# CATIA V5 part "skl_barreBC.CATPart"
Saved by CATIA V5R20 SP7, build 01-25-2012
Part number: skl_barreBC
Publications: "Axe pivot BC/DC", "Axe pivot BC/AB", "Plan BC"
Bounding box of the stored display mesh (mm): x 0 to 0, y 12.857 to 72.857, z 18.811 to 18.811
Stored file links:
  U:\IAO_bon\skl_barreBC.CATPart
  U:\IAO_bon\skl_IAO.CATProduct
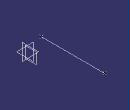
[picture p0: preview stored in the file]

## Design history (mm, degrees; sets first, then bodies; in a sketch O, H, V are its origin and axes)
Set1
  Point1 "Point B/G": linked copy from another document
  Point2 "Point C": linked copy from another document
  Plane1 "Plan Ref": linked copy from another document
Set2
  Line1: type PtPt, FirstPoint Point1, SecondPoint Point2
  Line2 "Axe pivot BC/DC": type Normal, RefPoint Point2, RefSkin Plane1, Start 0, End 20
  Line3 "Axe pivot BC/AB": type Normal, RefPoint Point1, RefSkin Plane1, Start 0, End 20
  Plane2 "Plan BC": type Normal, Curve Line2, RefPoint Point2
  Line4 "Axe pivot GC/FG": type Normal, RefPoint Point1, RefSkin Plane2, Start 0, End 20
Body1 (main body)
